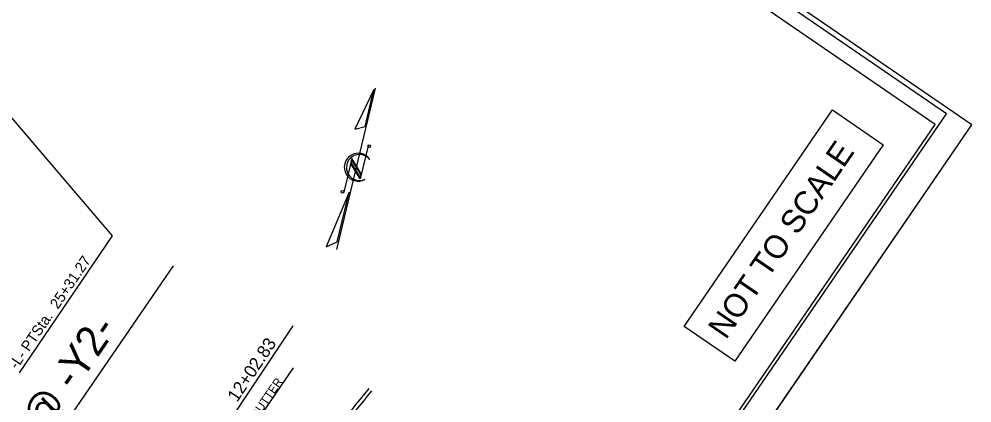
# Model space of a CAD drawing. Extents: x 1975573 to 1977432, y 778300 to 780514.
# Drawn here: x 1976648 to 1977432, y 779460 to 779776 of the extents above; entities that cross this region are included whole.
import ezdxf

# ---------------------------------------------------------------- set-up
doc = ezdxf.new("R2010")
doc.units = 0
for name, color, linetype in [('Prop Conc 2ft 6in Curb and Gutter', 7, 'Continuous'), ('Prop Dimension', 7, 'Continuous'), ('Prop Dimension Text', 7, 'Continuous'), ('Prop EOT', 7, 'Continuous'), ('Prop Horizontal Alignment Station Label', 7, 'Continuous'), ('Prop Lane Arrow CELL', 7, 'Continuous'), ('Sheet Cutting Line CELL', 7, 'Continuous'), ('Sheet North Arrow CELL', 7, 'Continuous'), ('Sheet Plot Border Inside CELL', 7, 'Continuous'), ('Sheet Plot Border Outside CELL', 7, 'Continuous'), ('Sheet Sticker Preliminary CELL', 7, 'Continuous'), ('Sheet Typical CELL', 7, 'Continuous')]:
    doc.layers.add(name, color=color, linetype=linetype)

msp = doc.modelspace()

# ---------------------------------------------------------------- linework, layer by layer
at = {"layer": 'Prop Conc 2ft 6in Curb and Gutter'}
msp.add_arc((1981863.71, 775482.94), 6340.12, 141.013904, 142.623065, dxfattribs=at)
at = {"layer": 'Prop Dimension'}
for p, q in [((1976423.7, 779059.98), (1976774.88, 779572.85)), ((1976805.64, 779389.71), (1976873.59, 779488.87))]:
    msp.add_line(p, q, dxfattribs=at)
at = {"layer": 'Prop EOT'}
msp.add_arc((1981863.71, 775482.94), 6337.13, 141.013915, 142.623075, dxfattribs=at)
at = {"layer": 'Prop Horizontal Alignment Station Label'}
for p, q in [((1976638.47, 779698.11), (1976724.43, 779597.46)), ((1976724.43, 779597.46), (1976647.81, 779484.53)), ((1976785.44, 779391.66), (1976873.25, 779523.31))]:
    msp.add_line(p, q, dxfattribs=at)
at = {"layer": 'Prop Lane Arrow CELL'}
msp.add_line((1976724.43, 779597.46), (1976724.43, 779597.46), dxfattribs=at)
at = {"layer": 'Sheet Cutting Line CELL'}
msp.add_line((1976480.18, 778299.74), (1977432.06, 779688.9), dxfattribs=at)
at = {"layer": 'Sheet North Arrow CELL'}
for p, q in [((1976909.2, 779586.28), (1976941.03, 779719.01)), ((1976934.96, 779671.62), (1976928.42, 779644.38)), ((1976921.73, 779661.21), (1976915.09, 779633.52)), ((1976921.49, 779660.21), (1976920.89, 779657.72)), ((1976929.2, 779647.63), (1976921.49, 779660.21)), ((1976929.44, 779648.63), (1976921.73, 779661.21)), ((1976936.28, 779660.57), (1976936.4, 779660.44)), ((1976928.42, 779644.38), (1976920.71, 779656.96)), ((1976928.6, 779645.14), (1976920.89, 779657.72)), ((1976920.89, 779657.72), (1976928.6, 779645.14)), ((1976928.6, 779645.14), (1976929.2, 779647.63))]:
    msp.add_line(p, q, dxfattribs=at)
for points in [[(1976939.83, 779718.07), (1976923.99, 779685.42), (1976932.49, 779687.44)], [(1976919.33, 779633.3), (1976900.6, 779588.34), (1976909.53, 779592.46)]]:
    msp.add_lwpolyline(points, close=True, dxfattribs=at)
for centre in [(1976936.03, 779671.34), (1976913.99, 779633.74)]:
    msp.add_circle(centre, 1.11, dxfattribs=at)
for centre, radius, start, end in [((1976926.92, 779653.97), 11.47, 34.35328, 298.90732), ((1976928, 779653.72), 10.75, 39.6083, 295.14197)]:
    msp.add_arc(centre, radius, start, end, dxfattribs=at)
at = {"layer": 'Sheet Plot Border Inside CELL'}
msp.add_lwpolyline([(1976540.62, 780294.27), (1975598.63, 778919.54), (1976469.01, 778323.15), (1977410.99, 779697.88)], close=True, dxfattribs=at)
at = {"layer": 'Sheet Plot Border Outside CELL'}
msp.add_lwpolyline([(1976524.64, 780310.68), (1975572.77, 778921.51), (1976480.18, 778299.74), (1977432.06, 779688.9)], close=True, dxfattribs=at)
at = {"layer": 'Sheet Sticker Preliminary CELL'}
msp.add_lwpolyline([(1977195.08, 779522.91), (1977317.24, 779701.19), (1977359.07, 779672.53), (1977236.91, 779494.25)], close=True, dxfattribs=at)
at = {"layer": 'Sheet Typical CELL'}
msp.add_lwpolyline([(1976535.66, 780282.52), (1975687.78, 779045.14), (1976553.95, 778451.63), (1977401.82, 779689.01)], close=True, dxfattribs=at)

# ---------------------------------------------------------------- texts
at = {"layer": 'Prop Dimension'}
msp.add_text('END CURB & GUTTER', height=7, rotation=55.39071, dxfattribs=at).set_placement((1976809.04, 779396.14))
at = {"layer": 'Prop Dimension Text'}
msp.add_text('DETAIL OF ROUNDABOUT @ -Y2-', height=25, rotation=55.5983, dxfattribs=at).set_placement((1976426.44, 779079.33))
at = {"layer": 'Prop Horizontal Alignment Station Label'}
for s, height, rotation, p in [('-L- PTSta.  25+31.27', 8.75, 55.72568, (1976646.04, 779487.1)), ('-Y6- PTSta.  12+02.83', 10.5, 56.2746, (1976782.2, 779392.45))]:
    msp.add_text(s, height=height, rotation=rotation, dxfattribs=at).set_placement(p)
at = {"layer": 'Sheet Sticker Preliminary CELL'}
msp.add_text('NOT TO SCALE', height=19.2, rotation=55.58051, dxfattribs=at).set_placement((1977229.53, 779511.35))

doc.saveas('drawing.dxf')
